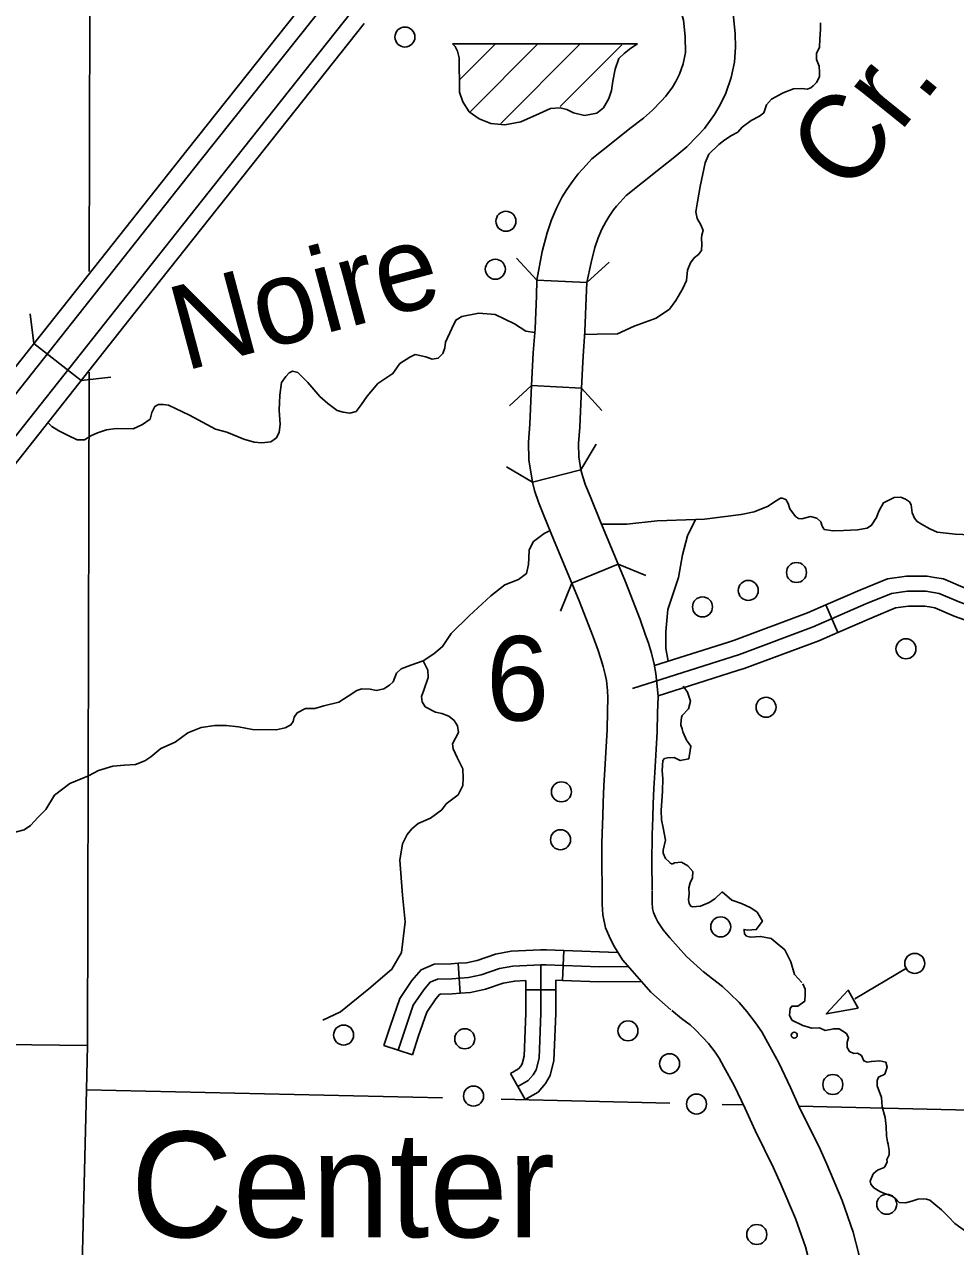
# Model space of a CAD drawing. Extents: x 1369979 to 1371646, y 379997 to 381064.
# Drawn here: x 1370912.7 to 1370967.2, y 380159.1 to 380230.7 of the extents above; entities that cross this region are included whole.
import ezdxf

# ---------------------------------------------------------------- set-up
doc = ezdxf.new("R2010")
doc.units = 0
doc.layers.add('R_Border Notes', color=7, linetype='Continuous')

msp = doc.modelspace()

# ---------------------------------------------------------------- linework, layer by layer
at = {"layer": 'R_Border Notes'}
for p, q in [((1370937.773, 380229.565), (1370948.601, 380229.565)), ((1370938.218, 380227.485), (1370940.257, 380229.524)), ((1370938.822, 380225.603), (1370942.729, 380229.51)), ((1370940.607, 380224.902), (1370945.234, 380229.529)), ((1370944.075, 380225.884), (1370947.699, 380229.508)), ((1370942.722, 380215.711), (1370942.722, 380215.711)), ((1370913.263, 380212.006), (1370913.055, 380213.751)), ((1370913.263, 380212.006), (1370916.027, 380209.833)), ((1370916.027, 380209.833), (1370917.772, 380210.041)), ((1370960.333, 380195.086), (1370959.631, 380196.698)), ((1370959.631, 380196.698), (1370959.631, 380196.698)), ((1370944.224, 380174.712), (1370944.292, 380176.469)), ((1370938.226, 380173.963), (1370938.106, 380175.717)), ((1370961.325, 380173.637), (1370964.354, 380175.421)), ((1370943.83, 380174.154), (1370942.072, 380174.154)), ((1370935.432, 380170.351), (1370933.76, 380170.894)), ((1370942.03, 380167.736), (1370941.164, 380169.266))]:
    msp.add_line(p, q, dxfattribs=at)
for points in [[(1370954.291, 380228.484), (1370954.339, 380229.37), (1370954.323, 380230.139), (1370954.228, 380231.131), (1370954.166, 380231.529), (1370953.982, 380232.242), (1370953.639, 380233.149), (1370953.312, 380234.024), (1370952.106, 380237.246), (1370950.845, 380240.414), (1370950.531, 380241.124)], [(1370947.852, 380239.938), (1370948.144, 380239.279), (1370949.373, 380236.191), (1370950.568, 380232.998), (1370950.896, 380232.118), (1370951.185, 380231.355), (1370951.293, 380230.936), (1370951.32, 380230.766), (1370951.397, 380229.968), (1370951.416, 380229.05)], [(1370922.214, 380223.314), (1370929.852, 380232.933)], [(1370930.634, 380232.315), (1370922.993, 380222.694)], [(1370916.545, 380231.607), (1370916.512, 380216.234)], [(1370924.185, 380221.746), (1370931.829, 380231.371)], [(1370924.965, 380221.125), (1370932.611, 380230.754)], [(1370959.33, 380230.795), (1370959.315, 380230.425), (1370959.286, 380229.833), (1370959.256, 380229.36), (1370959.094, 380228.99), (1370959.094, 380228.649), (1370959.241, 380228.25), (1370959.271, 380227.895), (1370959.271, 380227.629), (1370959.094, 380227.288), (1370958.887, 380227.096), (1370958.754, 380226.972), (1370958.547, 380226.912), (1370958.236, 380226.942), (1370957.734, 380226.927), (1370957.142, 380226.691), (1370956.463, 380226.321), (1370956.167, 380225.98), (1370956.004, 380225.522), (1370955.753, 380225.329), (1370955.265, 380225.078), (1370954.733, 380224.678), (1370954.482, 380224.383)], [(1370937.773, 380229.565), (1370937.926, 380229.395), (1370938.072, 380229.137), (1370938.169, 380228.748), (1370938.169, 380228.166), (1370938.185, 380227.406), (1370938.185, 380226.726), (1370938.379, 380226.16), (1370938.751, 380225.577), (1370939.334, 380225.157), (1370940.013, 380224.898), (1370940.838, 380224.817), (1370941.777, 380224.995), (1370942.861, 380225.48), (1370943.524, 380225.772), (1370944.09, 380225.82), (1370944.478, 380225.707), (1370944.867, 380225.513), (1370945.497, 380225.367), (1370946.226, 380225.497), (1370946.614, 380225.82), (1370946.937, 380226.354), (1370947.083, 380226.823), (1370947.164, 380227.373), (1370947.293, 380228.069), (1370947.52, 380228.7), (1370947.827, 380228.991), (1370948.215, 380229.298), (1370948.601, 380229.565)], [(1370951.416, 380229.05), (1370951.273, 380228.391), (1370951.063, 380227.79), (1370950.853, 380227.351), (1370950.662, 380227.016), (1370950.27, 380226.484), (1370950, 380226.196), (1370949.483, 380225.664), (1370948.951, 380225.206), (1370948.158, 380224.596), (1370947.061, 380223.729), (1370945.941, 380222.822), (1370945.419, 380222.262), (1370945.137, 380221.943), (1370944.832, 380221.558), (1370944.473, 380221.02), (1370944.204, 380220.593), (1370943.865, 380219.943), (1370943.572, 380219.242), (1370943.31, 380218.481), (1370943.032, 380217.397), (1370942.722, 380215.711)], [(1370945.649, 380215.586), (1370945.893, 380216.759), (1370946.118, 380217.639), (1370946.311, 380218.198), (1370946.52, 380218.698), (1370946.747, 380219.132), (1370946.932, 380219.427), (1370947.202, 380219.832), (1370947.383, 380220.06), (1370947.588, 380220.291), (1370947.944, 380220.674), (1370948.892, 380221.441), (1370949.961, 380222.286), (1370950.801, 380222.933), (1370951.492, 380223.528), (1370952.121, 380224.174), (1370952.527, 380224.609), (1370953.123, 380225.418), (1370953.451, 380225.994), (1370953.775, 380226.67), (1370954.098, 380227.593), (1370954.291, 380228.484)], [(1370954.482, 380224.383), (1370954.102, 380224.199), (1370953.718, 380223.933), (1370953.363, 380223.666), (1370952.786, 380223.089), (1370952.565, 380222.586), (1370952.269, 380221.196), (1370952.121, 380220.308), (1370952.018, 380219.716), (1370952.106, 380219.332), (1370952.313, 380218.962), (1370952.461, 380218.636), (1370952.373, 380218.37), (1370952.358, 380218.163), (1370952.373, 380217.822), (1370952.358, 380217.453), (1370952.18, 380217.216), (1370951.929, 380217.024), (1370951.707, 380216.742), (1370951.53, 380216.313), (1370951.471, 380215.692), (1370951.264, 380215.233), (1370950.85, 380214.523), (1370950.48, 380214.02)], [(1370916.068, 380215.547), (1370922.214, 380223.314)], [(1370922.993, 380222.694), (1370916.85, 380214.93)], [(1370918.046, 380213.987), (1370924.185, 380221.746)], [(1370918.829, 380213.37), (1370924.965, 380221.125)], [(1370942.722, 380215.711), (1370941.533, 380217.007)], [(1370946.944, 380216.774), (1370945.649, 380215.585)], [(1370906.985, 380204.079), (1370916.068, 380215.547)], [(1370942.722, 380215.711), (1370942.685, 380214.81), (1370942.608, 380212.869), (1370942.506, 380211.457), (1370942.466, 380210.693), (1370942.411, 380209.543)], [(1370942.722, 380215.711), (1370945.649, 380215.585)], [(1370945.649, 380215.585), (1370945.612, 380214.692), (1370945.533, 380212.706), (1370945.43, 380211.275), (1370945.392, 380210.546), (1370945.337, 380209.402)], [(1370916.85, 380214.93), (1370907.764, 380203.458)], [(1370908.955, 380202.508), (1370918.046, 380213.987)], [(1370950.48, 380214.02), (1370949.7, 380213.495), (1370948.414, 380213.021), (1370947.438, 380212.578), (1370946.241, 380212.548), (1370945.526, 380212.531)], [(1370909.733, 380201.886), (1370918.829, 380213.37)], [(1370942.592, 380212.65), (1370942.073, 380212.74), (1370941.408, 380213.155), (1370940.269, 380213.702), (1370939.323, 380213.791), (1370938.318, 380213.598), (1370937.967, 380213.38), (1370937.742, 380212.888), (1370937.358, 380212.089), (1370937.328, 380211.749), (1370937.21, 380211.424), (1370936.944, 380211.142), (1370936.589, 380211.098), (1370936.219, 380211.231)], [(1370936.219, 380211.231), (1370935.587, 380211.367), (1370935.276, 380211.205), (1370934.7, 380210.835), (1370934.286, 380210.243), (1370933.754, 380209.903), (1370933.399, 380209.666), (1370932.778, 380208.926), (1370932.438, 380208.408), (1370932.128, 380208.024), (1370931.758, 380207.935), (1370931.374, 380207.979), (1370931.019, 380208.083), (1370930.487, 380208.497), (1370930.014, 380208.911), (1370929.305, 380209.725), (1370928.713, 380210.317)], [(1370916.499, 380210.323), (1370916.415, 380170.909), (1370916.35, 380168.312), (1370915.894, 380150.153)], [(1370928.713, 380210.317), (1370928.406, 380210.381), (1370928.214, 380210.292), (1370928.022, 380210.085), (1370927.77, 380209.73), (1370927.667, 380208.99), (1370927.623, 380208.102), (1370927.682, 380207.274), (1370927.637, 380206.815), (1370927.475, 380206.489), (1370927.149, 380206.253), (1370926.617, 380206.194), (1370926.174, 380206.223), (1370925.568, 380206.401), (1370924.563, 380206.815), (1370923.898, 380206.992)], [(1370941.106, 380208.363), (1370942.409, 380209.542)], [(1370942.411, 380209.543), (1370942.302, 380207.287), (1370942.228, 380206.225), (1370942.246, 380205.204), (1370942.458, 380203.886)], [(1370945.337, 380209.402), (1370942.411, 380209.543)], [(1370945.298, 380204.611), (1370945.173, 380205.375), (1370945.159, 380206.149), (1370945.227, 380207.114), (1370945.337, 380209.402)], [(1370945.335, 380209.396), (1370946.515, 380208.093)], [(1370923.898, 380206.992), (1370922.38, 380207.806), (1370921.153, 380208.398), (1370920.842, 380208.442), (1370920.561, 380208.428), (1370920.34, 380208.324), (1370920.177, 380207.969), (1370920.074, 380207.584), (1370919.63, 380207.274), (1370919.083, 380207.007), (1370918.093, 380207.037), (1370917.516, 380206.948), (1370916.984, 380206.785), (1370916.6, 380206.593), (1370916.23, 380206.371), (1370915.802, 380206.371), (1370915.284, 380206.623), (1370914.723, 380206.889), (1370914.309, 380207.14), (1370914.08, 380207.374)], [(1370946.195, 380206.122), (1370945.298, 380204.611)], [(1370942.459, 380203.887), (1370940.947, 380204.784)], [(1370942.458, 380203.886), (1370945.298, 380204.611)], [(1370945.298, 380204.611), (1370945.4, 380204.211), (1370945.556, 380203.722), (1370945.832, 380203.06), (1370946.443, 380201.562), (1370947.472, 380199.089)], [(1370942.458, 380203.886), (1370942.584, 380203.398), (1370942.804, 380202.71), (1370943.124, 380201.942), (1370943.734, 380200.446), (1370944.767, 380197.966)], [(1370948.306, 380191.812), (1370954.572, 380193.806), (1370958.891, 380195.417), (1370961.975, 380196.76), (1370963.477, 380197.377), (1370964.416, 380197.511), (1370965.489, 380197.511), (1370966.267, 380197.377), (1370967.474, 380196.867), (1370969.325, 380196.196), (1370970.29, 380195.927), (1370971.202, 380195.9), (1370972.409, 380196.196), (1370973.563, 380196.813), (1370974.072, 380197.136), (1370975.843, 380198.908), (1370977.774, 380201.404), (1370980.081, 380204.067)], [(1370956.255, 380202.481), (1370955.442, 380202.155), (1370954.673, 380201.992), (1370952.527, 380201.726), (1370952.01, 380201.696)], [(1370961.487, 380201.104), (1370960.676, 380201.06), (1370960.055, 380201.03), (1370959.537, 380201.119), (1370959.418, 380201.311), (1370959.344, 380201.563), (1370959.108, 380201.785), (1370958.738, 380201.874), (1370958.22, 380201.741), (1370958.043, 380201.755), (1370957.865, 380201.874), (1370957.525, 380202.318), (1370957.436, 380202.644), (1370957.288, 380202.881), (1370957.081, 380202.955), (1370956.977, 380202.955), (1370956.637, 380202.733), (1370956.255, 380202.481)], [(1370968.099, 380200.808), (1370967.212, 380200.837), (1370966.161, 380200.956), (1370965.718, 380201.163), (1370965.244, 380201.43), (1370964.978, 380201.578), (1370964.83, 380201.785), (1370964.682, 380202.096), (1370964.623, 380202.555), (1370964.534, 380202.733), (1370964.297, 380202.896), (1370964.016, 380203.014), (1370963.632, 380202.984), (1370963.01, 380202.674), (1370962.744, 380202.2), (1370962.596, 380201.815), (1370962.315, 380201.37), (1370962.049, 380201.193), (1370961.487, 380201.104)], [(1370952.01, 380201.696), (1370949.764, 380201.622), (1370947.974, 380201.43), (1370946.497, 380201.43)], [(1370952.01, 380201.696), (1370951.539, 380200.75), (1370951.243, 380199.625), (1370951.007, 380198.307), (1370950.385, 380196.441), (1370950.267, 380195.153), (1370950.267, 380194.146), (1370950.402, 380193.402)], [(1370943.488, 380201.049), (1370943.136, 380200.882), (1370942.515, 380200.423), (1370942.264, 380199.919), (1370942.249, 380199.431), (1370942.219, 380199.061)], [(1370942.219, 380199.061), (1370942.105, 380198.536), (1370941.632, 380198.181), (1370940.848, 380197.87), (1370940.019, 380197.233), (1370938.747, 380196.064), (1370937.697, 380195.027), (1370937.194, 380194.257), (1370936.676, 380193.842), (1370936.055, 380193.428), (1370935.33, 380193.176), (1370934.768, 380192.964), (1370934.501, 380192.698)], [(1370947.472, 380199.089), (1370944.767, 380197.966)], [(1370947.472, 380199.089), (1370949.097, 380198.418)], [(1370949.473, 380179.99), (1370949.449, 380181.7), (1370949.449, 380182.166), (1370949.457, 380182.665), (1370949.472, 380183.236), (1370949.512, 380184.25), (1370949.52, 380185.05), (1370949.565, 380185.95), (1370949.619, 380186.893), (1370949.762, 380189.271), (1370949.786, 380190.387), (1370949.812, 380191.339), (1370949.765, 380191.946), (1370949.687, 380192.679), (1370949.591, 380193.229), (1370949.428, 380193.872), (1370949.251, 380194.455), (1370949.061, 380194.994), (1370948.763, 380195.849), (1370947.907, 380198.044), (1370947.472, 380199.089)], [(1370959.631, 380196.698), (1370961.633, 380197.569), (1370963.245, 380198.232), (1370964.354, 380198.39), (1370965.564, 380198.39), (1370966.002, 380198.315)], [(1370966.002, 380198.315), (1370966.516, 380198.226), (1370967.795, 380197.685), (1370969.593, 380197.034), (1370970.423, 380196.803), (1370971.109, 380196.783), (1370971.55, 380196.89)], [(1370944.095, 380196.342), (1370944.766, 380197.966)], [(1370944.767, 380197.966), (1370945.19, 380196.949), (1370946.014, 380194.834), (1370946.296, 380194.024), (1370946.467, 380193.542), (1370946.604, 380193.088), (1370946.724, 380192.616), (1370946.784, 380192.27), (1370946.847, 380191.679), (1370946.879, 380191.265), (1370946.858, 380190.458), (1370946.835, 380189.39), (1370946.695, 380187.066), (1370946.64, 380186.108), (1370946.591, 380185.138), (1370946.583, 380184.321), (1370946.544, 380183.333), (1370946.528, 380182.726), (1370946.52, 380182.188), (1370946.52, 380181.68), (1370946.543, 380179.95)], [(1370953.936, 380194.526), (1370954.285, 380194.637), (1370958.561, 380196.232), (1370959.631, 380196.698)], [(1370965.703, 380196.583), (1370965.414, 380196.633), (1370964.479, 380196.633), (1370963.71, 380196.523), (1370962.318, 380195.95), (1370960.333, 380195.086)], [(1370971.968, 380195.183), (1370971.296, 380195.018), (1370970.158, 380195.052), (1370969.057, 380195.358), (1370967.153, 380196.049), (1370966.018, 380196.528), (1370965.703, 380196.583)], [(1370949.605, 380193.148), (1370953.936, 380194.526)], [(1370954.469, 380192.851), (1370954.859, 380192.975), (1370959.22, 380194.602), (1370960.333, 380195.086)], [(1370937.414, 380185.048), (1370938.109, 380185.584), (1370938.39, 380186.132), (1370938.405, 380186.562), (1370938.376, 380187.11), (1370938.05, 380187.761), (1370937.814, 380188.279), (1370937.784, 380188.575), (1370937.961, 380188.901), (1370938.124, 380189.227), (1370938.065, 380189.627), (1370937.873, 380189.938), (1370937.562, 380190.189), (1370937.148, 380190.338), (1370936.778, 380190.426), (1370936.171, 380190.737), (1370935.994, 380191.019), (1370935.964, 380191.33), (1370936.097, 380191.7), (1370936.349, 380192.455), (1370936.334, 380192.87), (1370936.055, 380193.428)], [(1370934.501, 380192.698), (1370934.294, 380192.194), (1370934.087, 380192.002), (1370933.762, 380191.78), (1370933.333, 380191.691), (1370932.948, 380191.765), (1370932.474, 380191.78), (1370932.179, 380191.691), (1370931.676, 380191.365), (1370931.113, 380191.01)], [(1370949.813, 380191.369), (1370954.469, 380192.851)], [(1370951.281, 380191.934), (1370951.536, 380191.584), (1370951.711, 380191.06), (1370951.597, 380190.606), (1370951.222, 380190.215), (1370951.19, 380190.111), (1370951.139, 380189.74), (1370951.146, 380189.664), (1370951.228, 380189.448), (1370951.291, 380189.194)], [(1370931.113, 380191.01), (1370930.244, 380190.788), (1370929.711, 380190.64), (1370929.178, 380190.625), (1370928.69, 380190.373), (1370928.498, 380190.136), (1370928.439, 380189.87), (1370928.32, 380189.677), (1370927.98, 380189.499), (1370927.462, 380189.381), (1370926.072, 380189.411), (1370925.243, 380189.559), (1370924.533, 380189.647), (1370923.867, 380189.647), (1370923.054, 380189.514)], [(1370923.054, 380189.514), (1370922.273, 380189.203), (1370921.548, 380188.655), (1370920.705, 380188.3), (1370920.113, 380187.797), (1370919.773, 380187.574), (1370919.21, 380187.352), (1370918.574, 380187.323), (1370917.894, 380187.263), (1370917.05, 380186.997), (1370916.474, 380186.701)], [(1370951.276, 380189.238), (1370951.47, 380188.781), (1370951.724, 380188.436), (1370951.697, 380188.167), (1370951.618, 380187.694), (1370951.115, 380187.586), (1370950.764, 380187.762), (1370950.366, 380187.751), (1370950.194, 380187.707), (1370950.094, 380187.587), (1370950.054, 380186.991), (1370950.095, 380186.543), (1370950.076, 380185.788), (1370950.04, 380185.211)], [(1370916.474, 380186.701), (1370915.367, 380186.248), (1370914.465, 380185.552), (1370913.976, 380184.723), (1370913.518, 380184.264), (1370913.074, 380183.79), (1370912.704, 380183.538), (1370912.245, 380183.419), (1370911.476, 380183.39), (1370910.973, 380183.464), (1370910.485, 380183.804), (1370909.967, 380184.278), (1370909.405, 380184.885), (1370908.665, 380185.344)], [(1370950.04, 380185.219), (1370949.988, 380184.67), (1370950.021, 380184.122), (1370950.111, 380183.648), (1370950.257, 380182.932), (1370950.101, 380182.339), (1370950.101, 380182.171), (1370950.243, 380181.844), (1370950.636, 380181.503)], [(1370932.887, 380174.209), (1370934.233, 380175.367), (1370934.796, 380176.345), (1370934.996, 380178.142), (1370934.84, 380179.706), (1370934.692, 380181.761), (1370934.855, 380182.709), (1370935.121, 380183.257), (1370935.402, 380183.582), (1370935.757, 380183.908), (1370936.482, 380184.204), (1370937.148, 380184.708), (1370937.414, 380185.048)], [(1370950.506, 380181.568), (1370950.686, 380181.529), (1370950.769, 380181.602), (1370951.188, 380181.628), (1370951.561, 380181.43), (1370951.854, 380181.088), (1370951.826, 380180.727), (1370951.696, 380180.418), (1370951.61, 380180.124), (1370951.624, 380179.785), (1370951.596, 380179.423), (1370951.639, 380179.211), (1370951.724, 380179.055), (1370951.826, 380179.021), (1370952.298, 380179.057), (1370952.804, 380179.265), (1370953.129, 380179.486), (1370953.567, 380179.899)], [(1370950.567, 380172.991), (1370949.395, 380174.031), (1370948.293, 380175.276), (1370947.736, 380175.925), (1370947.262, 380176.68), (1370947.029, 380177.127), (1370946.727, 380177.788), (1370946.585, 380178.542), (1370946.535, 380179.172), (1370946.543, 380179.986)], [(1370949.473, 380179.955), (1370949.466, 380179.274), (1370949.493, 380178.93), (1370949.54, 380178.68), (1370949.662, 380178.414), (1370949.806, 380178.138), (1370950.101, 380177.667), (1370950.501, 380177.201), (1370951.471, 380176.105), (1370952.512, 380175.182)], [(1370958.229, 380174.585), (1370957.801, 380175.054), (1370957.577, 380175.796), (1370957.243, 380176.497), (1370956.792, 380176.865), (1370956.426, 380177.162), (1370955.813, 380177.288), (1370955.226, 380177.244), (1370954.99, 380177.301), (1370954.864, 380177.442), (1370954.845, 380177.66), (1370954.848, 380177.7), (1370955.047, 380177.662), (1370955.562, 380177.684), (1370955.92, 380178.173), (1370955.616, 380178.706), (1370955.245, 380178.966), (1370954.69, 380179.22), (1370954.137, 380179.414), (1370953.567, 380179.899)], [(1370938.106, 380175.717), (1370938.59, 380175.75), (1370939.229, 380175.887), (1370940.3, 380176.254), (1370941.212, 380176.424), (1370942.93, 380176.508), (1370943.277, 380176.508), (1370944.292, 380176.469)], [(1370944.292, 380176.469), (1370947.436, 380176.346)], [(1370933.76, 380170.894), (1370934.125, 380172.016), (1370934.688, 380173.65), (1370935.397, 380174.698), (1370935.939, 380175.338), (1370936.699, 380175.657), (1370937.69, 380175.689), (1370938.106, 380175.717)], [(1370934.596, 380170.622), (1370934.958, 380171.736), (1370935.481, 380173.253), (1370936.098, 380174.166), (1370936.474, 380174.609), (1370936.889, 380174.784), (1370937.734, 380174.811), (1370938.713, 380174.878), (1370939.464, 380175.039), (1370940.524, 380175.401), (1370941.315, 380175.549), (1370942.951, 380175.63), (1370943.26, 380175.63), (1370946.358, 380175.509), (1370948.078, 380175.526)], [(1370941.597, 380168.501), (1370942.214, 380168.85), (1370942.495, 380169.186), (1370942.67, 380169.481), (1370942.844, 380170.152), (1370942.951, 380172.784), (1370942.951, 380175.63)], [(1370952.459, 380175.227), (1370952.991, 380174.797), (1370953.584, 380174.348), (1370954.026, 380173.934), (1370954.551, 380173.409), (1370955.014, 380172.891), (1370955.519, 380172.234), (1370955.887, 380171.696), (1370956.238, 380171.064), (1370956.879, 380169.88), (1370957.56, 380168.436), (1370958.134, 380167.178), (1370959.217, 380164.998), (1370959.692, 380163.958), (1370960.587, 380161.829), (1370961.242, 380159.97), (1370961.575, 380158.683), (1370961.861, 380157.49), (1370962.187, 380156.108), (1370962.931, 380153.295), (1370962.98, 380153.124), (1370963.859, 380150.543), (1370964.255, 380149.314)], [(1370938.226, 380173.963), (1370938.836, 380174.005), (1370939.7, 380174.19), (1370940.748, 380174.549), (1370941.418, 380174.674), (1370942.072, 380174.706)], [(1370942.072, 380174.154), (1370942.072, 380174.706)], [(1370943.83, 380174.154), (1370943.83, 380174.728)], [(1370943.83, 380174.728), (1370944.224, 380174.712)], [(1370944.224, 380174.712), (1370946.345, 380174.63), (1370948.842, 380174.655)], [(1370958.28, 380174.507), (1370958.423, 380174.189), (1370958.423, 380173.926), (1370958.4, 380173.499), (1370957.989, 380173.197), (1370957.639, 380173.197), (1370957.542, 380173.07), (1370957.511, 380172.683), (1370957.644, 380172.387), (1370958.294, 380172.062), (1370958.812, 380171.919), (1370959.258, 380171.943), (1370959.594, 380171.772)], [(1370932.887, 380174.209), (1370931.215, 380172.88), (1370930.18, 380172.391)], [(1370935.432, 380170.351), (1370935.792, 380171.457), (1370936.274, 380172.857), (1370936.799, 380173.634), (1370937.008, 380173.88), (1370937.08, 380173.911), (1370937.778, 380173.933), (1370938.226, 380173.963)], [(1370941.164, 380169.266), (1370941.643, 380169.537), (1370941.775, 380169.695), (1370941.85, 380169.822), (1370941.97, 380170.282), (1370942.072, 380172.801), (1370942.072, 380174.154)], [(1370942.03, 380167.736), (1370942.785, 380168.163), (1370943.215, 380168.676), (1370943.489, 380169.141), (1370943.718, 380170.023), (1370943.83, 380172.766), (1370943.83, 380174.154)], [(1370961.467, 380148.416), (1370961.078, 380149.622), (1370960.183, 380152.249), (1370960.106, 380152.518), (1370959.344, 380155.397), (1370959.011, 380156.812), (1370958.732, 380157.975), (1370958.437, 380159.114), (1370957.852, 380160.774), (1370957.008, 380162.782), (1370956.572, 380163.738), (1370955.489, 380165.917), (1370954.902, 380167.203), (1370954.264, 380168.556), (1370953.669, 380169.656), (1370953.392, 380170.155), (1370953.147, 380170.513), (1370952.758, 380171.018), (1370952.421, 380171.396), (1370951.988, 380171.829), (1370951.693, 380172.106), (1370951.187, 380172.489), (1370950.62, 380172.946)], [(1370959.594, 380171.772), (1370960.097, 380171.876), (1370960.423, 380171.876), (1370960.852, 380171.594), (1370960.97, 380171.343), (1370960.881, 380171.091), (1370960.881, 380170.78), (1370961.029, 380170.543), (1370961.266, 380170.439), (1370961.488, 380170.454), (1370961.725, 380170.306), (1370961.858, 380169.995), (1370962.05, 380169.921), (1370962.301, 380169.966), (1370962.79, 380169.995), (1370963.145, 380169.921), (1370963.234, 380169.625), (1370963.086, 380169.225), (1370962.716, 380169.048), (1370962.642, 380168.855), (1370962.642, 380168.529), (1370962.893, 380167.848), (1370962.938, 380167.3)], [(1370885.378, 380171.27), (1370916.415, 380170.909)], [(1370916.35, 380168.312), (1370937.195, 380167.83)], [(1370940.629, 380167.75), (1370950.508, 380167.522)], [(1370953.572, 380167.451), (1370954.799, 380167.423)], [(1370958.05, 380167.347), (1370973.896, 380166.981)], [(1370962.233, 380162.959), (1370962.411, 380163.379), (1370962.662, 380163.601), (1370963.047, 380163.749), (1370963.121, 380163.868), (1370963.225, 380164.09), (1370963.21, 380164.223), (1370963.343, 380164.505), (1370963.343, 380164.741), (1370963.313, 380164.978), (1370963.284, 380165.112), (1370963.254, 380165.26), (1370963.195, 380165.615), (1370963.165, 380166.163), (1370963.106, 380166.681), (1370962.938, 380167.3)], [(1370968.24, 380159.745), (1370967.885, 380159.967), (1370967.189, 380160.471), (1370966.819, 380160.871), (1370966.405, 380161.271), (1370966.065, 380161.552), (1370965.725, 380161.833), (1370965.532, 380161.907), (1370965.34, 380161.922), (1370965.015, 380161.907), (1370964.66, 380161.774), (1370964.29, 380161.685), (1370963.935, 380161.715), (1370963.728, 380161.922), (1370963.52, 380162.085), (1370963.077, 380162.233), (1370962.796, 380162.351), (1370962.44, 380162.559), (1370962.263, 380162.781), (1370962.233, 380162.959)]]:
    msp.add_lwpolyline(points, dxfattribs=at)
msp.add_lwpolyline([(1370961.52, 380173.092), (1370960.945, 380174.139), (1370959.661, 380172.753)], close=True, dxfattribs=at)
for centre, radius in [((1370934.991, 380229.957), 0.586), ((1370940.905, 380219.168), 0.586), ((1370940.284, 380216.358), 0.586), ((1370957.917, 380198.6), 0.586), ((1370955.093, 380197.55), 0.586), ((1370952.414, 380196.583), 0.586), ((1370964.327, 380194.131), 0.586), ((1370956.133, 380190.709), 0.586), ((1370944.153, 380185.754), 0.586), ((1370944.103, 380182.95), 0.586), ((1370953.478, 380177.847), 0.586), ((1370964.838, 380175.708), 0.586), ((1370948.051, 380171.758), 0.586), ((1370931.401, 380171.512), 0.586), ((1370938.494, 380171.292), 0.586), ((1370957.789, 380171.504), 0.176), ((1370950.486, 380169.835), 0.586), ((1370960.045, 380168.616), 0.586), ((1370939.008, 380167.94), 0.586), ((1370952.062, 380167.473), 0.586), ((1370963.202, 380161.603), 0.586), ((1370955.593, 380159.83), 0.586)]:
    msp.add_circle(centre, radius, dxfattribs=at)

# ---------------------------------------------------------------- texts
for s, rotation, p in [('Cr.', 51.10017, (1370960.971, 380220.611)), ('Noire', 14.94554, (1370922.087, 380210.387))]:
    msp.add_text(s, height=4.95, rotation=rotation, dxfattribs=at).set_placement(p)
for s, height, p in [('6', 4.95, (1370939.744, 380189.927)), ('Center', 6.1875, (1370918.937, 380159.668))]:
    msp.add_text(s, height=height, dxfattribs=at).set_placement(p)

doc.saveas('drawing.dxf')
